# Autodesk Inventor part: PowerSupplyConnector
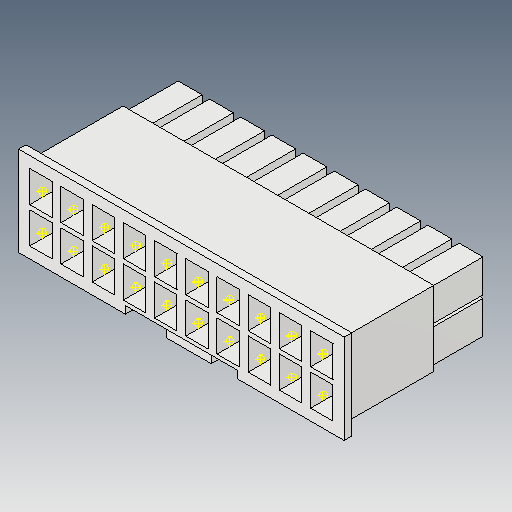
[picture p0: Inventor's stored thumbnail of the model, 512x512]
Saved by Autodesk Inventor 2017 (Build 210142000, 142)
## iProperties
Created: 2005-12
Part Number: PowerSupplyConnector
Material: Generic
Document SubType Name: Modeling
Designer: DanielSeverino
Categories: <MemberInstance><Categories><Category DisplayName="" Mnemonic="CABLEANDHARNESS" InternalName="e4a7e005-5e42-4d16-b293-125e7f0d0512"><Category DisplayName="" Mne
Density: 1 g/cm^3
Appearance: Default
GlobalPropertyList: <PropertyList/>
Author: Prof. Daniel Severino
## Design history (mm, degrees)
feature "Solid1"
sketch "Sketch1"
  geometry: L1 (42.134, -6.3)-(42.134, -10.5) reference; L2 (39.134, -6.3)-(42.134, -6.3) reference; L3 (39.134, -10.5)-(39.134, -6.3) reference; L4 (42.134, -10.5)-(39.134, -10.5) reference; L5 (41.634, -6.8)-(41.634, -10) reference; L6 (41.634, -10)-(39.634, -10) reference; L7 (39.634, -10)-(39.634, -6.8) reference; L8 (39.634, -6.8)-(41.634, -6.8) reference; L9 (37.952, -6.3)-(37.952, -10.5) reference; L10 (34.952, -6.3)-(37.952, -6.3) reference; L11 (34.952, -10.5)-(34.952, -6.3) reference; L12 (37.952, -10.5)-(34.952, -10.5) reference; L13 (37.452, -6.8)-(37.452, -10) reference; L14 (37.452, -10)-(35.452, -10) reference; L15 (35.452, -10)-(35.452, -6.8) reference; L16 (35.452, -6.8)-(37.452, -6.8) reference; L17 (42.134, -1.5)-(42.134, -5.7) reference; L18 (39.134, -1.5)-(42.134, -1.5) reference; L19 (39.134, -5.7)-(39.134, -1.5) reference; L20 (42.134, -5.7)-(39.134, -5.7) reference; L21 (41.634, -2)-(41.634, -5.2) reference; L22 (41.634, -5.2)-(39.634, -5.2) reference; L23 (39.634, -5.2)-(39.634, -2) reference; L24 (39.634, -2)-(41.634, -2) reference; L25 (41.634, -10)-(39.634, -6.8); L26 (41.634, -5.2)-(39.634, -2); L27 (37.452, -10)-(35.452, -6.8); 4 further points
  constraints: 6 end point, 3 midpoint, 2 parallel, 1 point on line
  dimensions: "d0" = 4.182 distance of point (36.452, -8.4) point (40.634, -8.4) (derived); "d1" = 4.8 distance of point (40.634, -3.6) point (40.634, -8.4) (derived)
  node "Projected Loop1"
  node "Projected Loop2"
  node "Projected Loop3"
node "1"
node "2"
node "3"
node "4"
node "5"
node "6"
node "7"
node "8"
node "9"
node "10"
node "11"
node "12"
node "13"
node "14"
node "15"
node "16"
node "17"
node "18"
node "19"
node "20"
body "Solid2"
